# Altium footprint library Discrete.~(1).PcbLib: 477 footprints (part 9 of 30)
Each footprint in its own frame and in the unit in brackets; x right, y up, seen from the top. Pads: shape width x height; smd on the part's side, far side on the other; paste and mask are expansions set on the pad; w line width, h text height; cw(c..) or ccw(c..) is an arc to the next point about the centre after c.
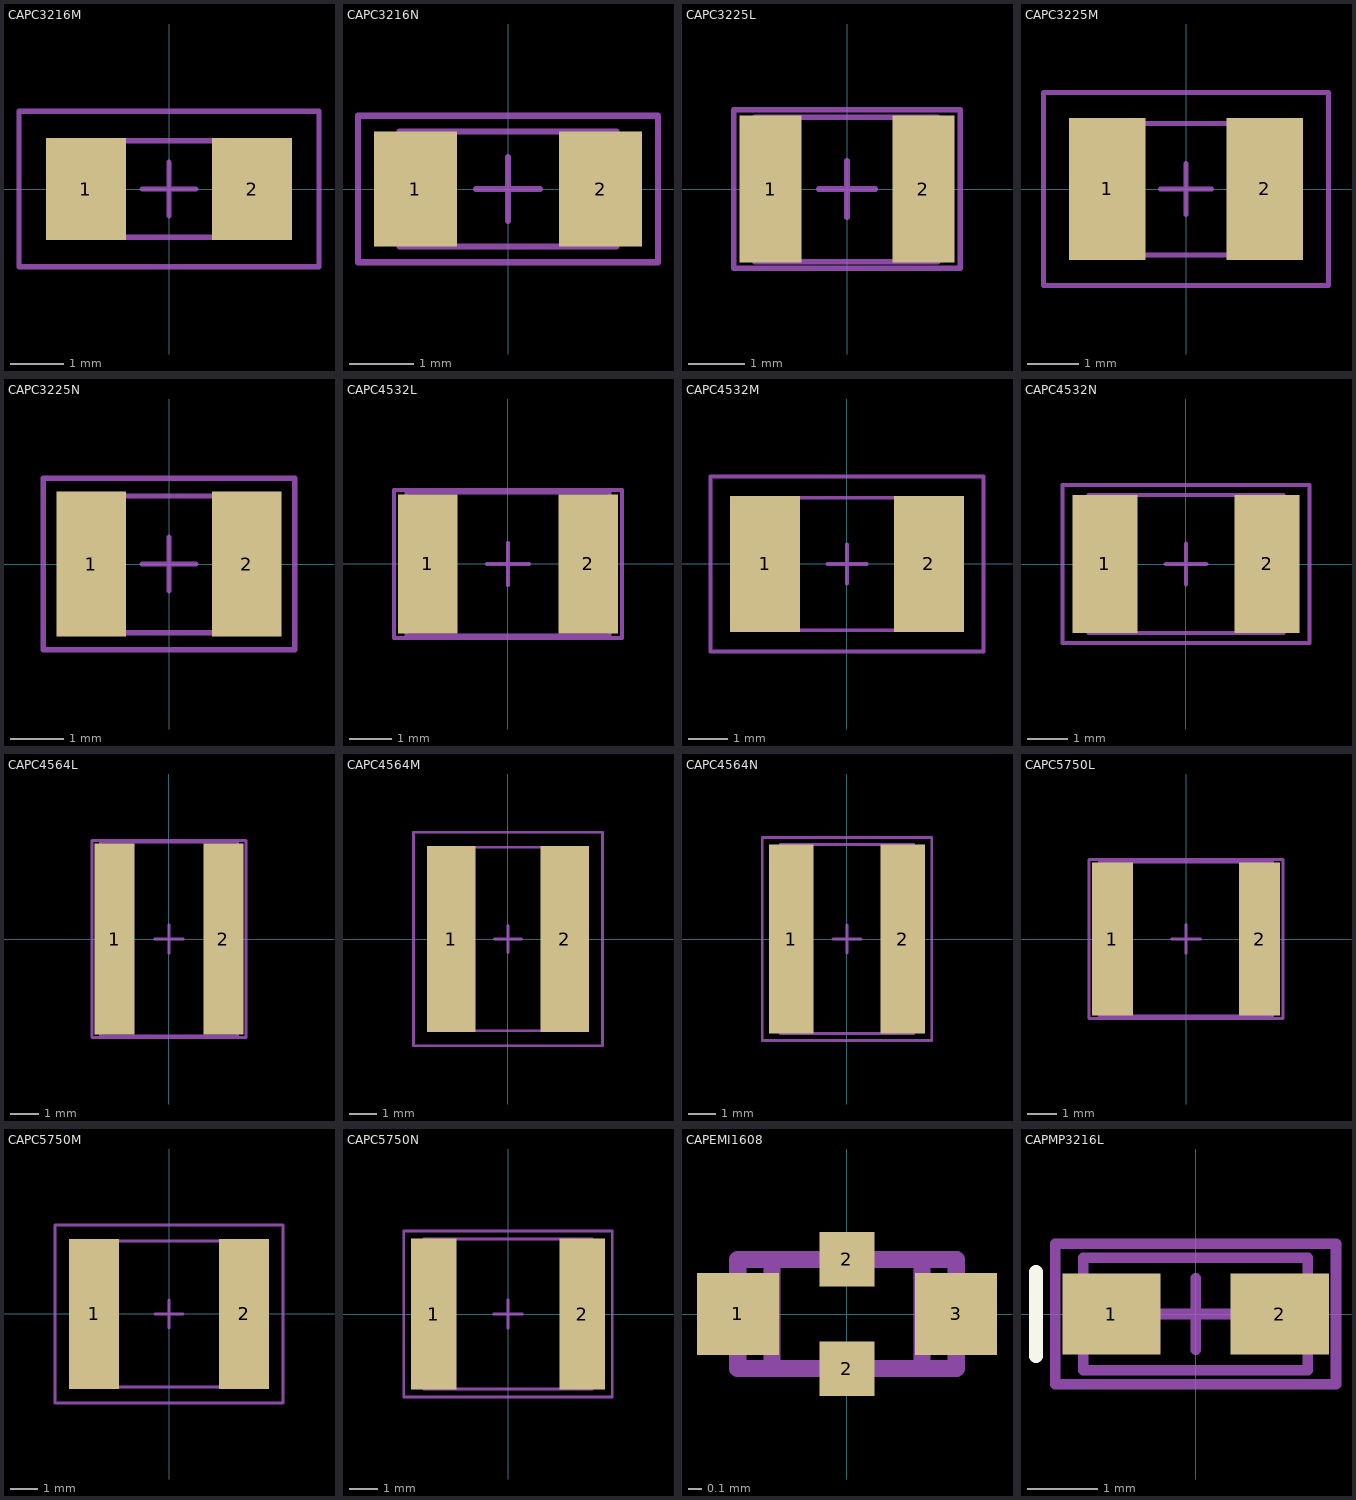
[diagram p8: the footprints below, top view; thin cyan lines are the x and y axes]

## CAPC3216M [mm] "Chip Capacitor, Body 3.2x1.6mm, IPC Low Density"
height 1.35
pads (2):
  rect 1.5x1.9 smd: 1(-1.55,0) 2(1.55,0)
Mechanical 13:
  lines w0.1: -1.7,-0.9 1.7,-0.9 1.7,0.9 -1.7,0.9 -1.7,-0.9
Mechanical 15:
  lines w0.1: -0.5,0 0.5,0 ; 0,-0.5 0,0.5 ; -2.8,-1.45 2.8,-1.45 2.8,1.45 -2.8,1.45 -2.8,-1.45
3D body "C 1206.STEP": height 1.21, standoff -0.01, extent -1.6,-0.81 1.6,0.81

## CAPC3216N [mm] "Chip Capacitor, Body 3.2x1.6mm, IPC Medium Density"
height 1.35
pads (2):
  rect 1.3x1.8 smd: 1(-1.45,0) 2(1.45,0)
Mechanical 13:
  lines w0.1: -1.7,-0.9 -1.7,0.9 1.7,0.9 1.7,-0.9 -1.7,-0.9
Mechanical 15:
  lines w0.1: -0.5,0 0.5,0 ; 0,-0.5 0,0.5 ; -2.35,-1.15 -2.35,1.15 2.35,1.15 2.35,-1.15 -2.35,-1.15
3D body "C 1206.STEP": height 1.21, standoff -0.01, extent -1.6,-0.81 1.6,0.81

## CAPC3225L [mm] "Chip Capacitor, Body 3.2x2.5mm, IPC High Density"
height 1.35
pads (2):
  rect 1.1x2.6 smd: 1(-1.35,0) 2(1.35,0)
Mechanical 13:
  lines w0.1: -1.626,-1.285 -1.626,1.27 1.6,1.27 1.6,-1.285 -1.626,-1.285
Mechanical 15:
  lines w0.1: -0.5,0 0.5,0 ; 0,-0.5 0,0.5 ; -2,-1.4 -2,1.4 2,1.4 2,-1.4 -2,-1.4
3D body "C 1210.STEP": height 1.54, standoff 0.01, extent -1.6,-1.285 1.6,1.285

## CAPC3225M [mm] "Chip Capacitor, Body 3.2x2.5mm, IPC Low Density"
height 1.35
pads (2):
  rect 1.5x2.8 smd: 1(-1.55,0) 2(1.55,0)
Mechanical 13:
  lines w0.1: -1.6,-1.295 1.6,-1.295 1.6,1.285 -1.6,1.285 -1.6,-1.295
Mechanical 15:
  lines w0.1: -0.5,0 0.5,0 ; 0,-0.5 0,0.5 ; -2.8,-1.9 2.8,-1.9 2.8,1.9 -2.8,1.9 -2.8,-1.9
3D body "C 1210.STEP": height 1.54, standoff 0.01, extent -1.6,-1.285 1.6,1.285

## CAPC3225N [mm] "Chip Capacitor, Body 3.2x2.5mm, IPC Medium Density"
height 1.35
pads (2):
  rect 1.3x2.7 smd: 1(-1.45,0) 2(1.45,0)
Mechanical 13:
  lines w0.1: -1.6,-1.285 1.6,-1.285 1.6,1.27 -1.6,1.27 -1.6,-1.285
Mechanical 15:
  lines w0.1: -0.5,0 0.5,0 ; 0,-0.5 0,0.5 ; -2.35,-1.6 2.35,-1.6 2.35,1.6 -2.35,1.6 -2.35,-1.6
3D body "C 1210.STEP": height 1.54, standoff 0.01, extent -1.6,-1.285 1.6,1.285

## CAPC4532L [mm] "Chip Capacitor, Body 4.5x3.2mm, IPC High Density"
height 1.35
pads (2):
  rect 1.4x3.3 smd: 1(-1.9,0) 2(1.9,0)
Mechanical 13:
  lines w0.1: -2.4,-1.7 2.4,-1.7 2.4,1.7 -2.4,1.7 -2.4,-1.7
Mechanical 15:
  lines w0.1: -0.5,0 0.5,0 ; 0,-0.5 0,0.5 ; -2.7,-1.75 2.7,-1.75 2.7,1.75 -2.7,1.75 -2.7,-1.75
3D body: height 1.35, standoff 0, extent -2.4,-1.7 2.4,1.7

## CAPC4532M [mm] "Chip Capacitor, Body 4.5x3.2mm, IPC Low Density"
height 1.35
pads (2):
  rect 1.8x3.5 smd: 1(-2.1,0) 2(2.1,0)
Mechanical 13:
  lines w0.1: -2.4,-1.7 -2.4,1.7 2.4,1.7 2.4,-1.7 -2.4,-1.7
Mechanical 15:
  lines w0.1: -0.5,0 0.5,0 ; 0,-0.5 0,0.5 ; -3.5,-2.25 -3.5,2.25 3.5,2.25 3.5,-2.25 -3.5,-2.25
3D body: height 1.35, standoff 0, extent -2.4,-1.7 2.4,1.7

## CAPC4532N [mm] "Chip Capacitor, Body 4.5x3.2mm, IPC Medium Density"
height 1.35
pads (2):
  rect 1.6x3.4 smd: 1(-2,0) 2(2,0)
Mechanical 13:
  lines w0.1: -2.4,-1.7 -2.4,1.7 2.4,1.7 2.4,-1.7 -2.4,-1.7
Mechanical 15:
  lines w0.1: -0.5,0 0.5,0 ; 0,-0.5 0,0.5 ; -3.05,-1.95 -3.05,1.95 3.05,1.95 3.05,-1.95 -3.05,-1.95
3D body: height 1.35, standoff 0, extent -2.4,-1.7 2.4,1.7

## CAPC4564L [mm] "Chip Capacitor, Body 4.5x6.4mm, IPC High Density"
height 1.1
pads (2):
  rect 1.4x6.7 smd: 1(-1.9,0) 2(1.9,0)
Mechanical 13:
  lines w0.1: -2.4,-3.4 2.4,-3.4 2.4,3.4 -2.4,3.4 -2.4,-3.4
Mechanical 15:
  lines w0.1: -0.5,0 0.5,0 ; 0,-0.5 0,0.5 ; -2.7,-3.45 2.7,-3.45 2.7,3.45 -2.7,3.45 -2.7,-3.45
3D body: height 1.1, standoff 0, extent -2.4,-3.4 2.4,3.4

## CAPC4564M [mm] "Chip Capacitor, Body 4.5x6.4mm, IPC Low Density"
height 1.1
pads (2):
  rect 1.8x6.9 smd: 1(-2.1,0) 2(2.1,0)
Mechanical 13:
  lines w0.1: -2.4,-3.4 2.4,-3.4 2.4,3.4 -2.4,3.4 -2.4,-3.4
Mechanical 15:
  lines w0.1: -0.5,0 0.5,0 ; 0,-0.5 0,0.5 ; -3.5,-3.95 3.5,-3.95 3.5,3.95 -3.5,3.95 -3.5,-3.95
3D body: height 1.1, standoff 0, extent -2.4,-3.4 2.4,3.4

## CAPC4564N [mm] "Chip Capacitor, Body 4.5x6.4mm, IPC Medium Density"
height 1.1
pads (2):
  rect 1.6x6.8 smd: 1(-2,0) 2(2,0)
Mechanical 13:
  lines w0.1: -2.4,-3.4 2.4,-3.4 2.4,3.4 -2.4,3.4 -2.4,-3.4
Mechanical 15:
  lines w0.1: -0.5,0 0.5,0 ; 0,-0.5 0,0.5 ; -3.05,-3.65 3.05,-3.65 3.05,3.65 -3.05,3.65 -3.05,-3.65
3D body: height 1.1, standoff 0, extent -2.4,-3.4 2.4,3.4

## CAPC5750L [mm] "Chip Capacitor, Body 5.7x5.0mm, IPC High Density"
height 1.35
pads (2):
  rect 1.4x5.2 smd: 1(-2.5,0) 2(2.5,0)
Mechanical 13:
  lines w0.1: -2.95,-2.625 2.95,-2.625 2.95,2.625 -2.95,2.625 -2.95,-2.625
Mechanical 15:
  lines w0.1: -0.5,0 0.5,0 ; 0,-0.5 0,0.5 ; -3.3,-2.7 3.3,-2.7 3.3,2.7 -3.3,2.7 -3.3,-2.7
3D body: height 1.35, standoff 0, extent -2.95,-2.625 2.95,2.625

## CAPC5750M [mm] "Chip Capacitor, Body 5.7x5.0mm, IPC Low Density"
height 1.35
pads (2):
  rect 1.8x5.4 smd: 1(-2.7,0) 2(2.7,0)
Mechanical 13:
  lines w0.1: -2.95,-2.625 2.95,-2.625 2.95,2.625 -2.95,2.625 -2.95,-2.625
Mechanical 15:
  lines w0.1: -0.5,0 0.5,0 ; 0,-0.5 0,0.5 ; -4.1,-3.2 4.1,-3.2 4.1,3.2 -4.1,3.2 -4.1,-3.2
3D body: height 1.35, standoff 0, extent -2.95,-2.625 2.95,2.625

## CAPC5750N [mm] "Chip Capacitor, Body 5.7x5.0mm, IPC Medium Density"
height 1.35
pads (2):
  rect 1.6x5.3 smd: 1(-2.6,0) 2(2.6,0)
Mechanical 13:
  lines w0.1: -2.95,-2.625 -2.95,2.625 2.95,2.625 2.95,-2.625 -2.95,-2.625
Mechanical 15:
  lines w0.1: -0.5,0 0.5,0 ; 0,-0.5 0,0.5 ; -3.65,-2.9 -3.65,2.9 3.65,2.9 3.65,-2.9 -3.65,-2.9
3D body: height 1.35, standoff 0, extent -2.95,-2.625 2.95,2.625

## CAPEMI1608 [mm]
pads (4):
  rect 0.6x0.6 smd: 1(-0.8,0) 3(0.8,0)
  rect 0.4x0.4 smd: 2(0,-0.4) 2(0,0.4)
Mechanical 13:
  lines w0.127: -0.55,-0.4 -0.55,0.4 ; 0.55,-0.4 0.55,0.4 ; -0.8,-0.4 0.8,-0.4 0.8,0.4 -0.8,0.4 -0.8,-0.4
3D body: height 0.6, standoff 0, extent -0.8,-0.4 -0.55,0.4
3D body: height 0.6, standoff 0, extent 0.55,-0.4 0.8,0.4
3D body: height 0.6, standoff 0, extent -0.125,-0.4 0.125,-0.25
3D body: height 0.6, standoff 0, extent -0.125,0.25 0.125,0.4
3D body: height 0.6, standoff 0, extent -0.55,-0.4 0.55,0.4

## CAPMP3216L [mm] "Capacitor, polarized, Molded,  CASE A"
height 1.8
pads (2):
  rect 1.4x1.15 smd: 1(-1.2,0) 2(1.2,0)
Top Overlay:
  lines w0.2: -2.275,-0.6 -2.275,0.6
Mechanical 13:
  lines w0.15: -1.6,-0.8 -1.6,0.8 1.6,0.8 1.6,-0.8 -1.6,-0.8
Mechanical 15:
  lines w0.15: -0.508,0 0.508,0 ; 0,-0.508 0,0.508 ; -2,-1 -2,1 2,1 2,-1 -2,-1
3D body "CD A(3216).STEP": height 1.6, standoff -0.01, extent -1.6,-0.8 1.6,0.8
